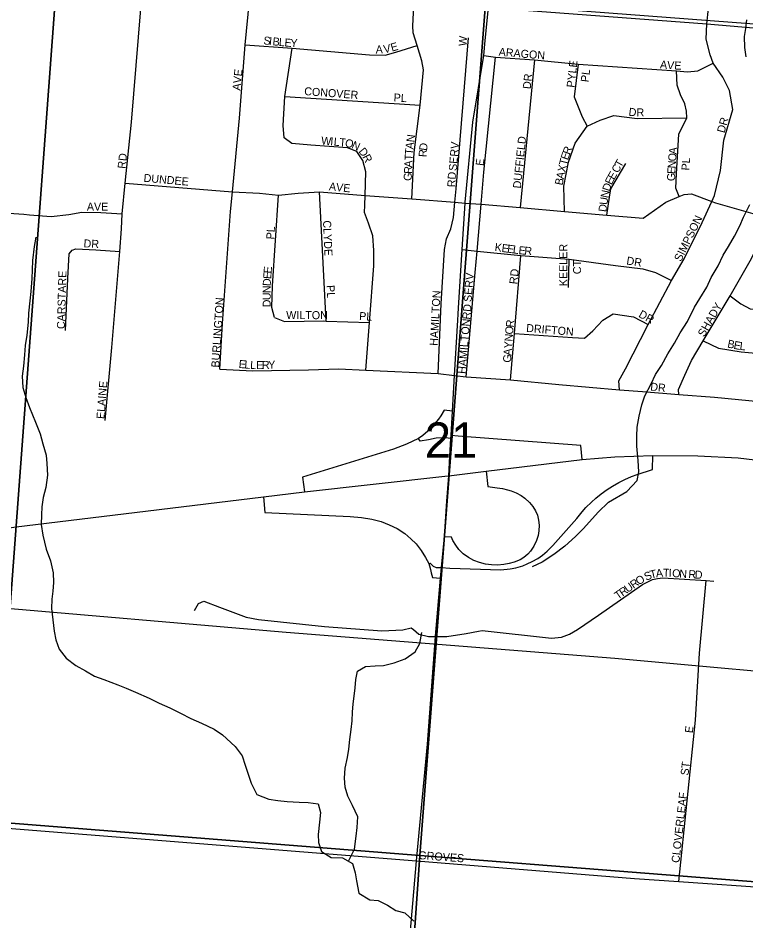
# Model space of a CAD drawing. Extents: x 0 to 34, y 0 to 22.
# Drawn here: x 6.347 to 7.208, y 18.975 to 20.042 of the extents above; entities that cross this region are included whole.
import ezdxf

# ---------------------------------------------------------------- set-up
doc = ezdxf.new("R2010")
doc.units = 0
for name, color, linetype in [('GM_X_City_Street', 7, 'Continuous'), ('GM_X_City_Street_Text', 7, 'Continuous'), ('GM_X_Interchange_Ramps', 7, 'Continuous'), ('GM_X_Interstate_Route', 7, 'Continuous'), ('GM_X_Minor_River', 7, 'Continuous'), ('GM_X_Rail_Line', 7, 'Continuous'), ('GM_X_Section', 7, 'Continuous'), ('GM_X_Section_Text', 7, 'Continuous'), ('GM_X_State_Route', 7, 'Continuous')]:
    doc.layers.add(name, color=color, linetype=linetype)

msp = doc.modelspace()

# ---------------------------------------------------------------- linework, layer by layer
at = {"layer": 'GM_X_City_Street'}
for points in [[(6.4498, 19.5665), (6.4576, 19.6527), (6.4669, 19.7663), (6.4691, 19.7932), (6.4697, 19.8107), (6.4734, 19.8471), (6.4808, 19.9192), (6.4945, 20.0871)], [(6.5853, 19.6269), (6.5885, 19.6809), (6.598, 19.8134), (6.6002, 19.8368), (6.6084, 19.9239), (6.6151, 20.0106), (6.6202, 20.0631), (6.6196, 20.0768)], [(6.8123, 19.8285), (6.8152, 19.8832), (6.8222, 19.9394), (6.826, 19.9811), (6.8243, 19.9916), (6.8186, 20.0097), (6.8138, 20.0246), (6.8135, 20.033), (6.8144, 20.0485), (6.8153, 20.0616)], [(6.9029, 20.0547), (6.9029, 20.0547), (7.1612, 20.0355), (7.2442, 20.0284), (7.4189, 20.0151), (7.4865, 20.0093)], [(7.0578, 19.6028), (7.057, 19.6133), (7.0651, 19.6273), (7.0919, 19.6798), (7.1195, 19.732), (7.1346, 19.7576), (7.1556, 19.8004), (7.1671, 19.8254), (7.1703, 19.8325), (7.1775, 19.8621), (7.1813, 19.8978), (7.1922, 19.9341), (7.188, 19.9564), (7.18, 19.9722), (7.1687, 19.9889), (7.1651, 19.9987), (7.1603, 20.0172), (7.1612, 20.0355), (7.1633, 20.0535)], [(6.8434, 19.6218), (6.847, 19.7042), (6.8511, 19.7684), (6.8535, 19.7813), (6.8586, 19.793), (6.8618, 19.8063), (6.8634, 19.8245), (6.8648, 19.8405), (6.8794, 20.0189)], [(6.6151, 20.0106), (6.6708, 20.0065), (6.7623, 19.9987), (6.7808, 19.9984), (6.7936, 20.002), (6.8186, 20.0097)], [(7.1281, 19.5971), (7.1279, 19.603), (7.1353, 19.62), (7.1431, 19.6374), (7.157, 19.6605), (7.1887, 19.7137), (7.2139, 19.7579), (7.2244, 19.7791), (7.2341, 19.7934), (7.2378, 19.8047), (7.2388, 19.8078), (7.2424, 19.8252), (7.2447, 19.8606), (7.2502, 19.9133), (7.2613, 19.9689), (7.2536, 19.9831), (7.2478, 19.9914), (7.2448, 19.9998), (7.2431, 20.009), (7.2435, 20.0157)], [(6.758, 19.6258), (6.7623, 19.6824), (6.7674, 19.7492), (6.7676, 19.7674), (6.7663, 19.7849), (6.7611, 19.7998), (6.7563, 19.8124), (6.7568, 19.8211), (6.7571, 19.8326), (6.758, 19.8603), (6.7544, 19.874), (6.7473, 19.8843), (6.7363, 19.8887), (6.6927, 19.8918), (6.6703, 19.8939), (6.6613, 19.9005), (6.6603, 19.9153), (6.6623, 19.9496), (6.6708, 20.0065)], [(6.8975, 19.9978), (6.9112, 19.996), (6.9574, 19.9928), (7.009, 19.9877), (7.1252, 19.9797), (7.1383, 19.9785), (7.1508, 19.9799), (7.1687, 19.9889)], [(6.8767, 19.618), (6.8872, 19.7414), (6.8895, 19.7667), (6.8944, 19.822), (6.8977, 19.8599), (6.9112, 19.996)], [(6.9574, 19.9928), (6.9405, 19.8183)], [(7.009, 19.9877), (7.0042, 19.9491), (7.0138, 19.9255), (7.0198, 19.9144)], [(7.1287, 19.8312), (7.1245, 19.841), (7.1255, 19.8581), (7.1283, 19.9048), (7.1377, 19.9242), (7.1371, 19.9323), (7.1353, 19.9409), (7.1302, 19.9516), (7.1261, 19.963), (7.1252, 19.9797)], [(6.6623, 19.9496), (6.8222, 19.9394)], [(6.9929, 19.8137), (6.992, 19.8436), (6.9977, 19.8717), (7.0055, 19.8944), (7.0198, 19.9144), (7.0351, 19.9214), (7.0514, 19.927), (7.0787, 19.9236), (7.1377, 19.9242)], [(7.0429, 19.8092), (7.0462, 19.8305), (7.0478, 19.8403), (7.0656, 19.8702)], [(6.4734, 19.8471), (6.6002, 19.8368), (6.6321, 19.8351), (6.6548, 19.8329), (6.678, 19.8353), (6.7031, 19.8366), (6.7571, 19.8326), (6.8123, 19.8285), (6.8634, 19.8245), (6.8754, 19.8235), (6.8944, 19.822), (6.9405, 19.8183), (6.9929, 19.8137), (7.0429, 19.8092), (7.0858, 19.8057), (7.1129, 19.8244), (7.1287, 19.8312), (7.1343, 19.8337), (7.143, 19.8343), (7.1671, 19.8254), (7.1714, 19.8238), (7.2378, 19.8047)], [(6.7109, 19.684), (6.7031, 19.8366)], [(6.6498, 19.6882), (6.6468, 19.7), (6.6475, 19.7258), (6.6548, 19.8329)], [(6.221, 19.8061), (6.2378, 19.8163), (6.2466, 19.8196), (6.2568, 19.8202), (6.2818, 19.8177), (6.3418, 19.8113), (6.3535, 19.8103), (6.36, 19.8097)], [(6.36, 19.8097), (6.3857, 19.8074), (6.4066, 19.8098), (6.4219, 19.8127), (6.4446, 19.8125), (6.4697, 19.8107)], [(6.4026, 19.6726), (6.4055, 19.7342), (6.4071, 19.7636), (6.4107, 19.7678), (6.4149, 19.7694), (6.4388, 19.7683), (6.4669, 19.7663)], [(6.8719, 19.7685), (6.8895, 19.7667), (6.9414, 19.7613), (6.9983, 19.7573), (7.0532, 19.7498), (7.0855, 19.7457), (7.1006, 19.7413), (7.1195, 19.732)], [(6.9291, 19.6144), (6.9337, 19.6691), (6.9414, 19.7613)], [(6.9975, 19.7238), (6.9983, 19.7573)], [(7.1887, 19.7137), (7.2015, 19.7045), (7.2125, 19.6986), (7.2398, 19.6953), (7.3187, 19.6898), (7.3399, 19.6885), (7.3505, 19.6853), (7.3621, 19.6726), (7.365, 19.6585), (7.3628, 19.6329)], [(6.6498, 19.6882), (6.6618, 19.6835), (6.7082, 19.6841), (6.7109, 19.684), (6.7623, 19.6824)], [(6.9337, 19.6691), (7.0022, 19.6645), (7.0166, 19.6639), (7.0265, 19.6722), (7.0381, 19.685), (7.0503, 19.6925), (7.0746, 19.6891), (7.0919, 19.6798)], [(7.157, 19.6605), (7.1751, 19.6519), (7.2017, 19.6474), (7.2881, 19.6396), (7.3628, 19.6329), (7.3898, 19.6305), (7.4069, 19.633), (7.4191, 19.6397), (7.4345, 19.6578)], [(6.5853, 19.6269), (6.6244, 19.625), (6.69, 19.6261), (6.7261, 19.6273), (6.758, 19.6258), (6.8434, 19.6218), (6.8629, 19.6196), (6.8767, 19.618), (6.9291, 19.6144), (6.9863, 19.6088), (7.0578, 19.6028), (7.085, 19.6005), (7.1281, 19.5971), (7.1703, 19.5938), (7.2799, 19.5835)], [(6.8913, 19.3172), (6.8957, 19.3179), (6.9777, 19.3088), (6.9893, 19.31), (6.9987, 19.3139), (7.0082, 19.3192), (7.033, 19.3362), (7.0853, 19.3726), (7.097, 19.3783), (7.103, 19.3795), (7.1094, 19.3805), (7.1604, 19.377), (7.1694, 19.3764)], [(7.1282, 19.0212), (7.1477, 19.2119), (7.1527, 19.2913), (7.1604, 19.377)], [(6.5555, 19.3419), (6.5601, 19.3498), (6.5662, 19.3527), (6.5849, 19.3456), (6.6166, 19.3338), (6.631, 19.331), (6.7089, 19.3228), (6.7767, 19.3176), (6.8019, 19.3187), (6.8116, 19.3213), (6.8142, 19.3191)], [(6.8142, 19.3191), (6.8207, 19.3136), (6.8322, 19.3111), (6.8402, 19.3111), (6.8539, 19.3111), (6.8767, 19.3146), (6.8913, 19.3172)], [(5.8173, 19.1321), (6.2942, 19.0874), (6.8177, 19.0455)], [(6.8177, 19.0455), (7.0758, 19.0249), (7.1282, 19.0212), (7.2414, 19.0132), (7.2417, 19.0132)]]:
    msp.add_lwpolyline(points, dxfattribs=at)
at = {"layer": 'GM_X_Interchange_Ramps'}
for points in [[(6.8604, 19.5776), (6.8506, 19.5784), (6.8466, 19.5718), (6.844, 19.5679), (6.8417, 19.565), (6.8389, 19.5615), (6.8356, 19.558), (6.8327, 19.5551), (6.8286, 19.5514), (6.8254, 19.5488), (6.8201, 19.5449), (6.8062, 19.5384), (6.7905, 19.5325), (6.6832, 19.4994), (6.6854, 19.482)], [(7.0139, 19.5201), (7.0124, 19.5367), (6.8671, 19.5479), (6.8588, 19.5487)], [(6.8586, 19.5452), (6.8522, 19.5458), (6.8482, 19.5459), (6.8411, 19.5454), (6.8322, 19.5437), (6.8222, 19.5419), (6.8201, 19.5449)], [(6.8476, 19.3926), (6.8571, 19.3919), (6.9175, 19.3897), (6.9286, 19.3908), (6.9355, 19.3922), (6.9435, 19.3947), (6.9489, 19.3968), (6.9546, 19.3995), (6.9612, 19.4033), (6.9669, 19.4073), (6.9726, 19.412), (6.9792, 19.4186), (7.0074, 19.4506), (7.0138, 19.4585), (7.0183, 19.4635), (7.0248, 19.4699), (7.0301, 19.4747), (7.0364, 19.4797), (7.0435, 19.4849), (7.0497, 19.4889), (7.057, 19.4931), (7.0641, 19.4966), (7.072, 19.5001), (7.0788, 19.5027), (7.0971, 19.5083), (7.0975, 19.5249)], [(6.9003, 19.5063), (6.9021, 19.4882), (6.9133, 19.4869), (6.9195, 19.4858), (6.9255, 19.4844), (6.93, 19.4832), (6.9358, 19.4809), (6.9416, 19.4777), (6.9461, 19.4744), (6.9515, 19.4693), (6.9553, 19.4646), (6.9585, 19.4594), (6.9609, 19.4544), (6.9622, 19.4486), (6.9629, 19.4425), (6.9626, 19.4358), (6.9617, 19.4303), (6.9599, 19.4244), (6.9567, 19.4177), (6.9528, 19.4119), (6.9495, 19.4082), (6.9448, 19.4043), (6.9403, 19.4018), (6.9334, 19.399), (6.9273, 19.3971), (6.9212, 19.396), (6.9137, 19.3954), (6.9067, 19.3956), (6.8996, 19.3966), (6.8925, 19.3984), (6.8857, 19.401), (6.8794, 19.4043), (6.873, 19.4086), (6.8678, 19.414), (6.8642, 19.4189), (6.861, 19.4244), (6.8593, 19.4283), (6.8508, 19.4289)], [(6.6369, 19.476), (6.6383, 19.4577), (6.7393, 19.4527), (6.7528, 19.4516), (6.765, 19.4498), (6.776, 19.4469), (6.7857, 19.4431), (6.7949, 19.4386), (6.804, 19.4326), (6.811, 19.4266), (6.8175, 19.4205), (6.8235, 19.4125), (6.8287, 19.4042), (6.8326, 19.3971), (6.8333, 19.3947), (6.8345, 19.39), (6.8352, 19.3863), (6.8368, 19.3808), (6.8464, 19.3801)], [(6.8326, 19.3971), (6.8342, 19.3976), (6.8375, 19.3943), (6.8412, 19.3925), (6.8476, 19.3926)]]:
    msp.add_lwpolyline(points, dxfattribs=at)
at = {"layer": 'GM_X_Interstate_Route'}
for points in [[(6.8515, 19.5006), (6.856, 19.501), (6.9003, 19.5063), (7.0139, 19.5201), (7.0525, 19.5234), (7.0975, 19.5249), (7.1506, 19.5247), (7.1982, 19.5221), (7.2409, 19.5171), (7.2883, 19.5109), (7.3176, 19.5063), (7.3568, 19.4984), (7.3997, 19.4881), (7.4592, 19.4703), (7.5217, 19.4482), (7.6858, 19.3921), (7.7744, 19.3608), (7.8161, 19.3516), (7.8255, 19.3496)], [(5.515, 19.2145), (5.6613, 19.2604), (5.7565, 19.2916), (5.8311, 19.3182), (5.8985, 19.3388), (5.98, 19.3651), (6.059, 19.3874), (6.1254, 19.4026), (6.1987, 19.4177), (6.2689, 19.4298), (6.3443, 19.4407), (6.4452, 19.453), (6.6369, 19.476), (6.6854, 19.482), (6.8515, 19.5006)]]:
    msp.add_lwpolyline(points, dxfattribs=at)
at = {"layer": 'GM_X_Minor_River'}
for points in [[(7.2078, 19.9965), (7.2063, 20.0075), (7.206, 20.0205), (7.2072, 20.0299), (7.2084, 20.0402)], [(7.045, 19.4698), (7.0666, 19.4826), (7.0788, 19.4954), (7.0807, 19.5057), (7.08, 19.519), (7.0783, 19.5361), (7.0783, 19.5478), (7.0788, 19.5585), (7.0811, 19.5714), (7.0842, 19.585), (7.0881, 19.5956), (7.0954, 19.6096), (7.1007, 19.6206), (7.1076, 19.6316), (7.1152, 19.6452), (7.1229, 19.6577), (7.1298, 19.6701), (7.1385, 19.6834), (7.1466, 19.7004), (7.1531, 19.7106), (7.1611, 19.7239), (7.1665, 19.7356), (7.1745, 19.7492), (7.1806, 19.7617), (7.1867, 19.7723), (7.194, 19.7844), (7.2001, 19.7965), (7.2047, 19.8067), (7.212, 19.8219)], [(6.3678, 19.7831), (6.3658, 19.7721), (6.3638, 19.7555), (6.3633, 19.7445), (6.3628, 19.7342), (6.3619, 19.719), (6.3607, 19.7077), (6.359, 19.6932), (6.3585, 19.6826), (6.3569, 19.6674), (6.3552, 19.6549), (6.3544, 19.6439), (6.3531, 19.6307), (6.3515, 19.6189), (6.3521, 19.6052), (6.3558, 19.5934), (6.3602, 19.5816), (6.3673, 19.5645), (6.3728, 19.5508), (6.3761, 19.5386), (6.3798, 19.5253), (6.3808, 19.5154), (6.3814, 19.5017), (6.3794, 19.4873), (6.3762, 19.4752), (6.3746, 19.4642), (6.3742, 19.4547), (6.374, 19.4433), (6.3758, 19.4308), (6.3798, 19.4141), (6.385, 19.4003), (6.3883, 19.3863), (6.3885, 19.3749), (6.3877, 19.3646), (6.3865, 19.3552), (6.386, 19.3441), (6.3877, 19.3308), (6.3895, 19.3172), (6.3913, 19.3069), (6.3954, 19.2959), (6.4036, 19.2852), (6.4149, 19.2767), (6.4262, 19.2702), (6.4371, 19.264), (6.448, 19.2601), (6.4646, 19.2539), (6.4744, 19.2497), (6.4854, 19.245), (6.5016, 19.2381), (6.5136, 19.2323), (6.5261, 19.2265), (6.5389, 19.2203), (6.551, 19.2141), (6.5634, 19.2083), (6.5785, 19.2014), (6.5883, 19.1945), (6.6033, 19.181), (6.6115, 19.17), (6.6152, 19.1589), (6.6192, 19.1471), (6.6222, 19.1376), (6.6289, 19.1243), (6.6432, 19.1185), (6.6538, 19.1172), (6.6651, 19.116), (6.6791, 19.1151), (6.6897, 19.1147), (6.7015, 19.1131), (6.7044, 19.1028), (6.7031, 19.0914), (6.7015, 19.077), (6.7018, 19.0675), (6.7055, 19.0568), (6.7171, 19.0495), (6.7304, 19.0494), (6.7421, 19.0425), (6.7454, 19.0315), (6.7468, 19.022), (6.7497, 19.0075), (6.7628, 18.9994), (6.7727, 18.9986), (6.7836, 18.9932), (6.7934, 18.987), (6.804, 18.9843), (6.8149, 18.9743)], [(7.045, 19.4698), (7.0328, 19.4581), (7.0153, 19.4385), (7.0058, 19.4294), (6.9932, 19.4178), (6.9803, 19.408), (6.9666, 19.3989), (6.9545, 19.3933)], [(6.7373, 19.0453), (6.7445, 19.0596), (6.7465, 19.0747), (6.7478, 19.0853), (6.7483, 19.0979), (6.7423, 19.1112), (6.7368, 19.1223), (6.7334, 19.1329), (6.7328, 19.1435), (6.7337, 19.1553), (6.7361, 19.1678), (6.7377, 19.1777), (6.7389, 19.189), (6.7405, 19.2008), (6.7418, 19.2114), (6.7422, 19.2213), (6.7431, 19.2312), (6.7443, 19.2406), (6.7452, 19.2501), (6.746, 19.26), (6.748, 19.2698), (6.7575, 19.2754), (6.7689, 19.2761), (6.7787, 19.2768), (6.7916, 19.2797), (6.8046, 19.2846), (6.8164, 19.2928), (6.8218, 19.3026), (6.8242, 19.3155)]]:
    msp.add_lwpolyline(points, dxfattribs=at)
at = {"layer": 'GM_X_Rail_Line'}
for points in [[(3.2423, 18.4276), (4.0405, 18.6814), (4.9172, 18.9741), (5.626, 19.2074), (5.8332, 19.2746), (5.9934, 19.3207), (6.0587, 19.3362), (6.1289, 19.3456), (6.1917, 19.3498), (6.2964, 19.3477), (6.6636, 19.3159)], [(6.6636, 19.3159), (7.0524, 19.2852), (7.6258, 19.2334), (7.6994, 19.2269), (7.7338, 19.2217), (7.7924, 19.2016), (7.8578, 19.1642), (8.0007, 19.0761), (8.2969, 18.8979), (8.814, 18.5835), (9.2779, 18.3027), (9.4, 18.2291)]]:
    msp.add_lwpolyline(points, dxfattribs=at)
at = {"layer": 'GM_X_Section'}
msp.add_lwpolyline([(6.9662, 20.9), (6.8995, 20.0595), (7.4047, 20.0213), (7.4767, 20.9)], dxfattribs=at)
for points in [[(5.8928, 20.1355), (6.3931, 20.0998), (6.3181, 19.0917), (5.819, 19.1295)], [(6.3931, 20.0998), (6.8995, 20.0595), (6.8218, 19.0519), (6.3181, 19.0917)], [(6.8995, 20.0595), (7.4047, 20.0213), (7.324, 19.0124), (6.8218, 19.0519)], [(6.3181, 19.0917), (6.8218, 19.0519), (6.7511, 18.0375), (6.2447, 18.0791)], [(6.8218, 19.0519), (7.324, 19.0124), (7.2561, 17.997), (6.7511, 18.0375)]]:
    msp.add_lwpolyline(points, close=True, dxfattribs=at)
at = {"layer": 'GM_X_State_Route'}
for points in [[(6.8992, 20.0158), (6.9029, 20.0547), (6.9046, 20.1145)], [(6.8667, 19.685), (6.8671, 19.6923), (6.8676, 19.6997), (6.8719, 19.7685), (6.8754, 19.8235), (6.8755, 19.8246), (6.8845, 19.9192), (6.8975, 19.9978), (6.8992, 20.0158)], [(6.8573, 19.524), (6.8586, 19.5452), (6.8588, 19.5487), (6.8604, 19.5776), (6.8629, 19.6196), (6.8667, 19.685)], [(6.8538, 19.4711), (6.856, 19.501), (6.8573, 19.524)], [(6.8177, 19.0455), (6.831, 19.1838), (6.8402, 19.3111), (6.8402, 19.3113), (6.8464, 19.3801), (6.8476, 19.3926), (6.8508, 19.4289), (6.8538, 19.4711)], [(6.7801, 18.5561), (6.7826, 18.5931), (6.7928, 18.7456), (6.7929, 18.7471), (6.8039, 18.8839), (6.804, 18.8852), (6.8177, 19.0455)]]:
    msp.add_lwpolyline(points, dxfattribs=at)

# ---------------------------------------------------------------- texts
at = {"layer": 'GM_X_City_Street_Text'}
for s, rotation, p in [('S', 354.4716, (6.6365, 20.0112)), ('I', 354.4416, (6.6431, 20.0105)), ('B', 354.4707, (6.6473, 20.0101)), ('L', 354.4776, (6.6547, 20.0094)), ('E', 354.7081, (6.6614, 20.0088)), ('W', 85.2379, (6.877, 20.0087)), ('Y', 358.3827, (6.6687, 20.0081)), ('A', 1.5299, (6.7697, 20.0003)), ('V', 10.52, (6.7797, 20.0007)), ('E', 15.7914, (6.7888, 20.0025)), ('ARAGON', 355.1588, (6.9148, 19.9978)), ('PYLE', 83.4775, (7.0047, 19.9596)), ('A', 355.427, (7.1056, 19.9828)), ('V', 355.4431, (7.1139, 19.9822)), ('E', 357.5545, (7.1226, 19.9815)), ('AVE', 84.0969, (6.6095, 19.9562)), ('DR', 83.9832, (6.9529, 19.9579)), ('PL', 82.8649, (7.0214, 19.966)), ('CONOVER', 355.7343, (6.6848, 19.9512)), ('PL', 356.4254, (6.7906, 19.9437)), ('D', 352.9888, (7.0683, 19.9269)), ('R', 1.8785, (7.0782, 19.9258)), ('DR', 74.4709, (7.1821, 19.9057)), ('W', 354.9152, (6.7048, 19.8928)), ('I', 354.9359, (6.7156, 19.8919)), ('L', 354.9391, (6.7197, 19.8915)), ('N', 83.165, (6.8151, 19.895)), ('DUFFIELD', 84.0353, (6.9412, 19.8404)), ('T', 354.9119, (6.7263, 19.8909)), ('O', 347.8671, (6.7327, 19.8904)), ('N', 335.8201, (6.7403, 19.8888)), ('A', 83.2978, (6.8141, 19.8867)), ('D', 82.3707, (6.8302, 19.8849)), ('SERV', 85.2328, (6.8654, 19.8612)), ('R', 70.021, (6.9992, 19.88)), ('RD', 83.982, (6.4737, 19.8637)), ('D', 308.2775, (6.7488, 19.8844)), ('R', 296.3478, (6.7537, 19.8783)), ('T', 87.1757, (6.8132, 19.8736)), ('T', 85.2409, (6.8135, 19.8802)), ('R', 86.6706, (6.8298, 19.8776)), ('E', 71.4268, (6.997, 19.8737)), ('O', 85.603, (7.1248, 19.8725)), ('A', 85.5898, (7.1255, 19.8808)), ('A', 87.1781, (6.8128, 19.8653)), ('E', 82.8783, (6.8971, 19.8671)), ('X', 77.9571, (6.9938, 19.8594)), ('T', 76.3746, (6.9955, 19.8674)), ('C', 60.4214, (7.0561, 19.8582)), ('T', 60.4214, (7.0598, 19.8647)), ('N', 85.6683, (7.1242, 19.8642)), ('PL', 86.4262, (7.1406, 19.8618)), ('DUNDEE', 354.9858, (6.4948, 19.8487)), ('G', 87.1791, (6.812, 19.8495)), ('R', 87.1771, (6.8124, 19.8578)), ('RD', 86.989, (6.8637, 19.842)), ('A', 77.9709, (6.9921, 19.8512)), ('E', 60.4214, (7.0516, 19.8502)), ('G', 89.2786, (7.1237, 19.8494)), ('E', 86.5276, (7.1238, 19.8576)), ('AVE', 354.0969, (6.714, 19.8387)), ('B', 77.9612, (6.9905, 19.8439)), ('E', 64.0342, (7.0487, 19.8443)), ('N', 78.4851, (7.0446, 19.8289)), ('D', 71.2596, (7.0462, 19.8367)), ('U', 82.0978, (7.0435, 19.8208)), ('AVE', 0, (6.428, 19.8145)), ('D', 82.0978, (7.0423, 19.8125)), ('SIMPSON', 63.8369, (7.1306, 19.7535)), ('PL', 86.4254, (6.6495, 19.7803)), ('CLYDE', 272.4881, (6.7073, 19.8028)), ('DR', 356.8215, (6.4239, 19.7712)), ('K', 352.6798, (6.9099, 19.7669)), ('E', 352.6837, (6.9181, 19.7658)), ('E', 352.6581, (6.9247, 19.765)), ('L', 352.6837, (6.9314, 19.7641)), ('E', 354.2058, (6.9382, 19.7632)), ('KEELER', 90, (6.9962, 19.7252)), ('R', 356.0362, (6.9452, 19.7625)), ('CT', 90, (7.0125, 19.7394)), ('DR', 351.0215, (7.0657, 19.751)), ('CARSTARE', 88.4097, (6.402, 19.6744)), ('E', 85.7898, (6.6459, 19.7334)), ('E', 85.7878, (6.6464, 19.74)), ('SERV', 85.2333, (6.8829, 19.7062)), ('RD', 83.9946, (6.937, 19.7271)), ('D', 86.8068, (6.6454, 19.7251)), ('N', 89.5409, (6.6454, 19.7169)), ('PL', 273.5746, (6.7114, 19.7262)), ('HAMILTON', 86.9064, (6.8429, 19.6545)), ('BURLINGTON', 86.188, (6.5845, 19.6287)), ('U', 89.9563, (6.6454, 19.7086)), ('D', 89.9563, (6.6454, 19.7002)), ('RD', 83.9946, (6.8812, 19.6854)), ('SHADY', 60.2568, (7.1581, 19.6644)), ('WILTON', 0, (6.6638, 19.6862)), ('PL', 356.1879, (6.7498, 19.6853)), ('DR', 330.6435, (7.0797, 19.6893)), ('HAMILTON', 85.364, (6.8762, 19.6212)), ('O', 84.3307, (6.9319, 19.6677)), ('R', 83.6974, (6.9328, 19.676)), ('DRIFTON', 355.2355, (6.9473, 19.6712)), ('N', 85.7555, (6.9313, 19.6595)), ('Y', 85.9097, (6.9307, 19.6512)), ('B', 348.8044, (7.185, 19.6528)), ('E', 349.1223, (7.1924, 19.6513)), ('L', 353.2059, (7.1997, 19.65)), ('A', 85.9057, (6.9301, 19.6428)), ('E', 355.132, (6.6073, 19.6286)), ('L', 355.1048, (6.614, 19.628)), ('L', 357.4985, (6.621, 19.6274)), ('E', 0.9086, (6.6283, 19.6271)), ('R', 1.7104, (6.6351, 19.6272)), ('Y', 1.6834, (6.6426, 19.6274)), ('G', 85.8879, (6.9295, 19.6345)), ('ELAINE', 85.4245, (6.4487, 19.5679)), ('DR', 353.9946, (7.094, 19.6019)), ('T', 13.5393, (7.0952, 19.3793)), ('A', 6.374, (7.1014, 19.3808)), ('T', 358.3057, (7.1093, 19.3817)), ('I', 357.0263, (7.1159, 19.3816)), ('O', 356.2601, (7.12, 19.3813)), ('N', 356.2383, (7.1284, 19.3808)), ('R', 356.2721, (7.1392, 19.3801)), ('D', 356.2383, (7.1467, 19.3796)), ('R', 34.9025, (7.0746, 19.3671)), ('O', 32.0471, (7.0806, 19.3713)), ('S', 24.3286, (7.0896, 19.3767)), ('R', 34.9413, (7.0616, 19.358)), ('U', 34.9329, (7.0677, 19.3623)), ('T', 34.9405, (7.0561, 19.3542)), ('E', 82.8514, (7.1445, 19.1963)), ('ST', 83.4209, (7.1395, 19.1463)), ('CLOVERLEAF', 83.5903, (7.1287, 19.0429)), ('GROVES', 355.8427, (6.8198, 19.0478))]:
    msp.add_text(s, height=0.00947, rotation=rotation, dxfattribs=at).set_placement(p)
at = {"layer": 'GM_X_Section_Text'}
msp.add_text('21', height=0.04186, rotation=0, dxfattribs=at).set_placement((6.8276, 19.5223))

doc.saveas('drawing.dxf')
